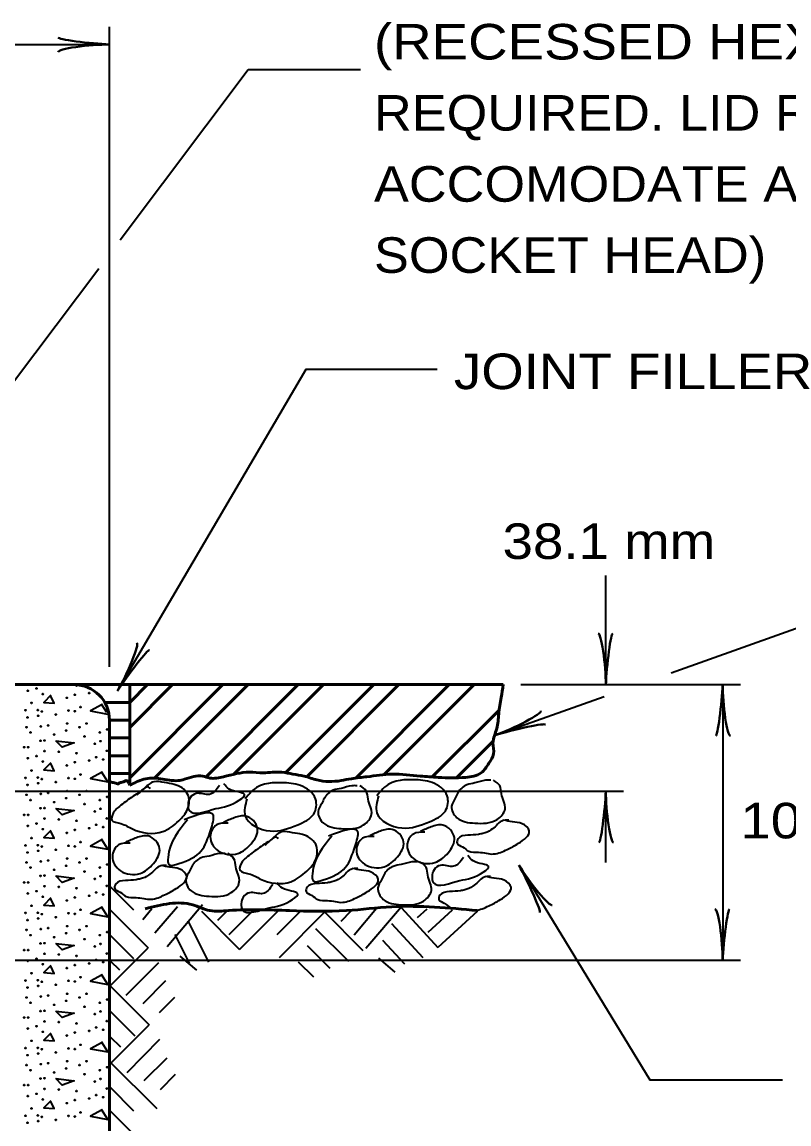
# Model space of a CAD drawing. Extents: x 442 to 1297, y -1132 to -588.
# Drawn here: x 669.8 to 721.6, y -913.9 to -839.5 of the extents above; entities that cross this region are included whole.
import ezdxf
from ezdxf.enums import TextEntityAlignment as Align

# ---------------------------------------------------------------- set-up
doc = ezdxf.new("R2010")
doc.units = 0
doc.header["$LTSCALE"] = 0.96
doc.layers.add('1', color=7, linetype='Continuous', lineweight=35)

msp = doc.modelspace()

# ---------------------------------------------------------------- linework, layer by layer
at = {"layer": '1'}
for p, q in [((675.7476, -883.0076), (675.7476, -839.8076)), ((570.1476, -841.0076), (675.7476, -841.0076)), ((676.4683, -854.1939), (685.1022, -842.7004)), ((685.1022, -842.7004), (692.699, -842.7004)), ((669.2683, -863.7786), (675.0268, -856.1125)), ((709.2608, -884.2076), (709.2608, -876.8344)), ((713.6649, -883.405), (726.825, -878.736)), ((703.5229, -884.2076), (718.3494, -884.2076)), ((717.1494, -884.2076), (717.1494, -902.8076)), ((701.7875, -887.6192), (709.1411, -885.01)), ((675.5776, -886.0926), (675.2138, -885.5267)), ((657.1476, -891.4076), (710.4608, -891.4076)), ((709.2608, -896.2076), (709.2608, -891.4076)), ((675.7956, -897.8235), (677.3796, -899.4075)), ((682.0321, -899.0677), (679.635, -901.908)), ((675.7956, -899.4075), (678.3636, -901.9755)), ((678.611, -899.3415), (677.9967, -900.0889)), ((680.3335, -899.2037), (678.8149, -900.9865)), ((681.9679, -899.5049), (684.5359, -902.0729)), ((683.6719, -899.5049), (683.0479, -900.1289)), ((685.3999, -899.5049), (683.8159, -901.0889)), ((687.1039, -899.5049), (684.5359, -902.0729)), ((688.6399, -899.5049), (687.0559, -901.0889)), ((690.3439, -899.5049), (687.1999, -902.6489)), ((690.2239, -899.5049), (692.8639, -902.1449)), ((692.0479, -899.5049), (691.3759, -900.2009)), ((693.7714, -899.3132), (692.2786, -901.1177)), ((695.4708, -899.2013), (693.0519, -902.023)), ((695.4663, -899.2778), (697.9177, -901.9573)), ((697.1686, -899.3535), (696.5175, -899.9491)), ((698.8949, -899.4302), (697.2421, -900.9423)), ((700.5972, -899.5059), (697.9177, -901.9573)), ((681.0476, -900.1544), (682.4436, -902.9475)), ((694.795, -900.329), (696.9027, -902.6329)), ((675.7956, -901.1115), (677.3796, -902.6955)), ((680.1595, -901.0726), (681.1306, -903.0156)), ((689.6479, -900.6569), (691.8799, -902.8649)), ((675.7956, -904.5435), (678.3636, -901.9755)), ((689.0959, -901.8089), (690.6319, -903.3449)), ((694.1923, -901.4553), (695.6586, -903.058)), ((661.3476, -902.8076), (718.3494, -902.8076)), ((675.7956, -902.8395), (676.4196, -903.4635)), ((680.5039, -902.5367), (681.615, -903.4831)), ((693.9159, -902.6584), (695.0196, -903.6133)), ((676.8756, -905.1675), (679.0836, -902.9595)), ((688.4959, -902.9129), (689.5279, -903.9209)), ((678.0276, -905.7195), (679.5636, -904.1835)), ((675.7956, -904.5435), (678.4356, -907.1595)), ((679.1316, -906.3435), (680.1636, -905.3115)), ((675.7956, -906.2475), (677.4516, -907.9035)), ((675.7956, -909.7995), (678.4356, -907.1595)), ((675.7956, -907.9755), (676.4916, -908.6475)), ((676.9476, -910.3755), (679.1556, -908.1435)), ((678.0996, -910.9275), (679.6356, -909.3915)), ((675.7956, -909.6795), (678.9396, -912.8235)), ((679.2036, -911.5275), (680.2116, -910.4955)), ((675.7956, -911.3835), (677.3796, -912.9675)), ((675.7956, -912.9675), (678.3636, -915.5355))]:
    msp.add_line(p, q, dxfattribs=at)
at = {"layer": '1', "lineweight": 53}
for p, q in [((673.3476, -884.2076), (668.5476, -884.2076)), ((673.3476, -884.2076), (702.3229, -884.2076)), ((677.1161, -884.2076), (677.1161, -891.0035)), ((677.1161, -885.4076), (678.3161, -884.2076)), ((677.1161, -887.1046), (680.0131, -884.2076)), ((677.1161, -890.4986), (683.4071, -884.2076)), ((678.7881, -890.5236), (685.1041, -884.2076)), ((682.2734, -890.4323), (688.4981, -884.2076)), ((684.104, -890.2987), (690.1951, -884.2076)), ((687.6375, -890.1592), (693.5891, -884.2076)), ((689.0695, -890.4242), (695.2861, -884.2076)), ((692.3704, -890.5173), (698.6801, -884.2076)), ((694.326, -890.2587), (700.3771, -884.2076)), ((675.4261, -885.4076), (677.1161, -885.4076)), ((697.5416, -890.4371), (702.0733, -885.9054)), ((675.7476, -980.7675), (675.7476, -886.6076)), ((675.7476, -886.6076), (675.7476, -980.8522)), ((675.7476, -886.6076), (677.1161, -886.6076)), ((675.7476, -887.8076), (677.1161, -887.8076)), ((699.1905, -890.4852), (701.6671, -888.0086)), ((675.7476, -889.0076), (677.1161, -889.0076)), ((675.7476, -890.2076), (677.1161, -890.2076))]:
    msp.add_line(p, q, dxfattribs=at)
at = {"layer": '1'}
for points in [[(676.293, -884.6252), (689.0246, -862.909), (697.8794, -862.909)], [(671.7818, -884.9267), (671.3258, -885.4067), (672.0218, -885.4547), (671.7818, -884.9747)], [(675.2618, -885.5507), (674.4698, -885.9827), (675.6105, -886.1922)], [(671.7818, -889.4867), (671.3258, -889.9667), (672.0218, -890.0147), (671.7818, -889.5347)], [(675.2618, -890.1107), (674.4698, -890.5427), (675.6458, -890.7587), (675.2138, -890.0867)], [(671.7818, -894.0467), (671.3258, -894.5267), (672.0218, -894.5747), (671.7818, -894.0947)], [(675.2618, -894.6707), (674.4698, -895.1027), (675.6458, -895.3187), (675.2138, -894.6467)], [(703.3988, -896.4034), (712.2296, -910.8809), (721.1831, -910.8809)], [(671.7818, -898.6067), (671.3258, -899.0867), (672.0218, -899.1347), (671.7818, -898.6547)], [(675.2618, -899.2307), (674.4698, -899.6627), (675.6458, -899.8787), (675.2138, -899.2067)], [(671.7818, -903.1667), (671.3258, -903.6467), (672.0218, -903.6947), (671.7818, -903.2147)], [(675.2618, -903.7907), (674.4698, -904.2227), (675.6458, -904.4387), (675.2138, -903.7667)], [(671.7818, -907.7267), (671.3258, -908.2067), (672.0218, -908.2547), (671.7818, -907.7747)], [(675.2618, -908.3507), (674.4698, -908.7827), (675.6458, -908.9987), (675.2138, -908.3267)], [(671.7818, -912.2867), (671.3258, -912.7667), (672.0218, -912.8147), (671.7818, -912.3347)], [(675.2618, -912.9107), (674.4698, -913.3427), (675.6458, -913.5587), (675.2138, -912.8867)]]:
    msp.add_lwpolyline(points, dxfattribs=at)
for points in [[(672.1178, -887.9987), (673.3658, -888.1427), (672.5498, -888.4307)], [(672.1178, -892.5587), (673.3658, -892.7027), (672.5498, -892.9907)], [(672.1178, -897.1187), (673.3658, -897.2627), (672.5498, -897.5507)], [(672.1178, -901.6787), (673.3658, -901.8227), (672.5498, -902.1107)], [(672.1178, -906.2387), (673.3658, -906.3827), (672.5498, -906.6707)], [(672.1178, -910.7987), (673.3658, -910.9427), (672.5498, -911.2307)]]:
    msp.add_lwpolyline(points, close=True, dxfattribs=at)
for centre in [(673.5268, -884.2752), (670.2255, -884.6195), (670.8139, -884.4661), (671.2525, -884.8421), (673.3996, -884.8899), (674.3697, -884.7785), (670.48, -885.4466), (672.8588, -885.0967), (673.7812, -885.7171), (670.0823, -885.9398), (670.2097, -886.4171), (670.9094, -885.9239), (670.9252, -886.3057), (671.1889, -886.0194), (672.1272, -886.2262), (672.986, -885.9558), (673.3996, -886.0035), (670.1459, -887.0852), (671.1161, -887.0216), (671.6182, -886.958), (672.8905, -886.8307), (673.7176, -887.0852), (674.1947, -886.8307), (675.5942, -887.2285), (670.4164, -887.4353), (671.0925, -887.9948), (671.3638, -887.9761), (672.0159, -887.5785), (672.827, -887.308), (674.0515, -887.7058), (675.1012, -887.4353), (675.149, -888.0239), (669.987, -888.4376), (670.2573, -888.4376), (671.3638, -888.6921), (672.334, -888.7398), (674.7672, -888.1989), (675.5624, -888.6762), (670.2255, -889.1795), (670.8139, -889.0261), (671.2525, -889.4021), (673.3996, -889.4499), (673.5268, -888.8352), (674.3697, -889.3385), (674.8468, -889.1057), (675.3238, -889.259), (670.48, -890.0066), (672.8588, -889.6567), (670.0823, -890.4998), (670.2097, -890.9771), (670.9094, -890.4839), (670.9252, -890.8657), (671.1889, -890.5794), (672.1272, -890.7862), (672.986, -890.5158), (673.3996, -890.5635), (673.7812, -890.2771), (670.1459, -891.6452), (671.1161, -891.5816), (671.6182, -891.518), (672.8905, -891.3907), (673.7176, -891.6452), (674.1947, -891.3907), (670.4164, -891.9953), (672.0159, -892.1385), (672.827, -891.868), (674.0515, -892.2658), (675.1012, -891.9953), (675.5942, -891.7885), (669.987, -892.9976), (670.2573, -892.9976), (671.0925, -892.5548), (671.3638, -892.5361), (674.7672, -892.7589), (675.149, -892.5839), (670.2255, -893.7395), (670.8139, -893.5861), (671.2525, -893.9621), (671.3638, -893.2521), (672.334, -893.2998), (673.5268, -893.3952), (674.3697, -893.8985), (674.8468, -893.6657), (675.3238, -893.819), (675.5624, -893.2362), (670.48, -894.5666), (672.8588, -894.2167), (673.3996, -894.0099), (670.0823, -895.0598), (670.9094, -895.0439), (670.9252, -895.4257), (671.1889, -895.1394), (672.1272, -895.3462), (672.986, -895.0758), (673.3996, -895.1235), (673.7812, -894.8371), (670.1459, -896.2052), (670.2097, -895.5371), (671.1161, -896.1416), (671.6182, -896.078), (672.8905, -895.9507), (673.7176, -896.2052), (674.1947, -895.9507), (670.4164, -896.5553), (672.0159, -896.6985), (672.827, -896.428), (674.0515, -896.8258), (675.1012, -896.5553), (675.5942, -896.3485), (669.987, -897.5576), (670.2573, -897.5576), (671.0925, -897.1148), (671.3638, -897.0961), (674.7672, -897.3189), (675.149, -897.1439), (670.2255, -898.2995), (670.8139, -898.1461), (671.3638, -897.8121), (672.334, -897.8598), (673.5268, -897.9552), (674.8468, -898.2257), (675.3238, -898.379), (675.5624, -897.7962), (670.48, -899.1266), (671.2525, -898.5221), (672.8588, -898.7767), (673.3996, -898.5699), (674.3697, -898.4585), (670.0823, -899.6198), (670.9094, -899.6039), (671.1889, -899.6994), (672.1272, -899.9062), (672.986, -899.6358), (673.3996, -899.6835), (673.7812, -899.3971), (670.2097, -900.0971), (670.9252, -899.9857), (671.6182, -900.638), (672.8905, -900.5107), (674.1947, -900.5107), (670.1459, -900.7652), (670.4164, -901.1153), (671.1161, -900.7016), (672.0159, -901.2585), (672.827, -900.988), (673.7176, -900.7652), (674.0515, -901.3858), (675.1012, -901.1153), (675.5942, -900.9085), (669.987, -902.1176), (670.2573, -902.1176), (671.0925, -901.6748), (671.3638, -901.6561), (674.7672, -901.8789), (675.149, -901.7039), (670.2255, -902.8595), (670.8139, -902.7061), (671.3638, -902.3721), (672.334, -902.4198), (673.5268, -902.5152), (674.8468, -902.7857), (675.5624, -902.3562), (671.2525, -903.0821), (672.8588, -903.3367), (673.3996, -903.1299), (674.3697, -903.0185), (675.3238, -902.939), (670.0823, -904.1798), (670.48, -903.6866), (670.9094, -904.1639), (671.1889, -904.2594), (672.986, -904.1958), (673.3996, -904.2435), (673.7812, -903.9571), (670.2097, -904.6571), (670.9252, -904.5457), (672.1272, -904.4662), (672.8905, -905.0707), (674.1947, -905.0707), (670.1459, -905.3252), (670.4164, -905.6753), (671.1161, -905.2616), (671.6182, -905.198), (672.0159, -905.8185), (672.827, -905.548), (673.7176, -905.3252), (675.1012, -905.6753), (675.5942, -905.4685), (671.0925, -906.2348), (671.3638, -906.2161), (674.0515, -905.9458), (674.7672, -906.4389), (675.149, -906.2639), (669.987, -906.6776), (670.2573, -906.6776), (670.8139, -907.2661), (671.3638, -906.9321), (672.334, -906.9798), (673.5268, -907.0752), (674.8468, -907.3457), (675.5624, -906.9162), (670.2255, -907.4195), (671.2525, -907.6421), (672.8588, -907.8967), (673.3996, -907.6899), (674.3697, -907.5785), (675.3238, -907.499), (670.0823, -908.7398), (670.48, -908.2466), (670.9094, -908.7239), (671.1889, -908.8194), (672.986, -908.7558), (673.3996, -908.8035), (673.7812, -908.5171), (670.2097, -909.2171), (670.9252, -909.1057), (672.1272, -909.0262), (670.1459, -909.8852), (670.4164, -910.2353), (671.1161, -909.8216), (671.6182, -909.758), (672.827, -910.108), (672.8905, -909.6307), (673.7176, -909.8852), (674.1947, -909.6307), (675.1012, -910.2353), (675.5942, -910.0285), (671.0925, -910.7948), (671.3638, -910.7761), (672.0159, -910.3785), (674.0515, -910.5058), (674.7672, -910.9989), (675.149, -910.8239), (669.987, -911.2376), (670.2573, -911.2376), (670.8139, -911.8261), (671.3638, -911.4921), (672.334, -911.5398), (673.5268, -911.6352), (675.5624, -911.4762), (670.2255, -911.9795), (671.2525, -912.2021), (672.8588, -912.4567), (673.3996, -912.2499), (674.3697, -912.1385), (674.8468, -911.9057), (675.3238, -912.059), (670.0823, -913.2998), (670.48, -912.8066), (670.9094, -913.2839), (672.986, -913.3158), (673.7812, -913.0771), (670.2097, -913.7771), (670.9252, -913.6657), (671.1889, -913.3794), (672.1272, -913.5862), (673.3996, -913.3635)]:
    msp.add_circle(centre, 0.0318, dxfattribs=at)
msp.add_arc((672.334, -884.1798), 0.0318, 241.23077, 298.76923, dxfattribs=at)
at = {"layer": '1', "lineweight": 53}
msp.add_arc((673.3476, -886.6076), 2.4, 0, 90, dxfattribs=at)
at = {"layer": '1', "lineweight": 40}
for centre, major_axis, ratio, start_param, end_param in [((674.4274, -841.3295), (2.1428, 0.1874), 0.122415, 0.8963533, 3.1415927), ((674.3922, -840.744), (2.1077, -0.2108), 0.07063, 3.1407148, 5.41811), ((708.9292, -882.8982), (0.1874, -2.1428), 0.122415, 0.8963533, 3.1415927), ((709.5147, -882.863), (-0.2108, -2.1077), 0.07063, 3.1407148, 5.41811), ((676.6692, -883.3279), (-0.9221, -1.9433), 0.122415, 0.8963533, 3.1415927), ((677.1921, -883.5937), (-1.2478, -1.7117), 0.07063, 3.1407148, 5.41811), ((716.8955, -885.5522), (0.2108, 2.1077), 0.07063, 3.1407148, 5.41811), ((716.8955, -885.5522), (0.2108, 2.1077), 0.07063, 3.1407148, 5.41811), ((717.481, -885.517), (-0.1874, 2.1428), 0.122415, 0.8963533, 3.1415927), ((717.481, -885.517), (-0.1874, 2.1428), 0.122415, 0.8963533, 3.1415927), ((702.9107, -886.8689), (-1.9568, -0.8931), 0.122415, 0.8963533, 3.1415927), ((703.1396, -887.4089), (-2.0569, -0.5061), 0.07063, 3.1407148, 5.41811), ((709.0069, -892.7522), (0.2108, 2.1077), 0.07063, 3.1407148, 5.41811), ((709.0069, -892.7522), (0.2108, 2.1077), 0.07063, 3.1407148, 5.41811), ((709.5924, -892.717), (-0.1874, 2.1428), 0.122415, 0.8963533, 3.1415927), ((709.5924, -892.717), (-0.1874, 2.1428), 0.122415, 0.8963533, 3.1415927), ((703.8822, -897.6835), (-0.9176, 1.9092), 0.07063, 3.1407148, 5.41811), ((704.3637, -897.3486), (-1.2758, 1.7318), 0.122415, 0.8963533, 3.1415927), ((716.8178, -901.4982), (0.1874, -2.1428), 0.122415, 0.8963533, 3.1415927), ((716.8178, -901.4982), (0.1874, -2.1428), 0.122415, 0.8963533, 3.1415927), ((717.4033, -901.463), (-0.2108, -2.1077), 0.07063, 3.1407148, 5.41811), ((717.4033, -901.463), (-0.2108, -2.1077), 0.07063, 3.1407148, 5.41811)]:
    msp.add_ellipse(centre, major_axis=major_axis, ratio=ratio, start_param=start_param, end_param=end_param, dxfattribs=at)
at = {"layer": '1', "lineweight": 53}
for points in [[(677.1161, -891.0035), (678.057, -890.5981), (679.1965, -890.5543), (680.3798, -890.6858), (680.818, -890.5981), (682.0451, -890.3789), (682.5272, -890.5105), (683.4476, -890.4228), (685.2006, -890.1159), (686.1209, -890.1597), (687.3919, -890.1159), (688.1369, -890.2474), (688.8819, -890.3789), (689.7584, -890.642), (691.38, -890.6858), (692.0812, -890.5543), (693.133, -890.4228), (694.8422, -890.2474), (696.7267, -890.3789), (697.9538, -890.4666), (699.7945, -890.4666), (700.8463, -890.1597), (701.3722, -889.5022), (701.679, -888.8884), (701.6352, -888.1431), (701.8981, -887.1786), (702.0296, -886.1703), (702.2049, -885.0743), (702.3229, -884.2076)], [(677.1161, -891.0035), (676.8737, -890.6858), (676.6984, -890.7735), (676.3916, -890.8612), (676.3478, -890.905), (676.304, -890.905), (676.1725, -890.8612), (675.9972, -890.8173), (675.7781, -890.7735)], [(700.5754, -899.4569), (694.8136, -899.2007), (691.7406, -899.4569), (687.8993, -899.4569), (683.802, -899.4569), (682.5216, -899.4569), (681.3693, -899.0726), (678.1682, -899.3288)]]:
    msp.add_spline(points, degree=3, dxfattribs=at)
at = {"layer": '1'}
for points in [[(678.5001, -891.2385), (678.3798, -891.1182), (678.079, -891.2385), (677.1167, -891.9001), (676.3347, -892.5016), (676.0941, -892.7422), (675.9137, -893.3437), (676.5152, -893.5843), (677.2971, -893.9452), (679.3422, -894.1256), (680.4248, -893.4038), (681.0263, -892.6219), (681.0263, -891.5994), (680.1241, -890.9377), (679.4625, -890.8175), (678.7407, -890.7573), (678.1392, -891.1783), (677.5978, -891.6595)], [(683.173, -891.0125), (682.5113, -891.614), (681.6091, -891.5539), (681.1881, -891.8546), (681.1279, -892.6967), (682.9324, -892.5764), (683.7143, -892.396), (684.8571, -891.614), (683.8346, -891.2531), (683.4737, -890.8922)], [(685.0268, -891.9178), (684.9065, -893.0606), (686.5907, -894.0832), (688.4553, -893.6621), (689.538, -892.9403), (689.6583, -891.9178), (688.6358, -891.0156), (687.3726, -890.8351), (686.3501, -890.8953), (685.8088, -891.0757), (684.9065, -891.9178)], [(693.9165, -891.7138), (693.7962, -892.8566), (695.4804, -893.8792), (697.345, -893.4581), (698.4277, -892.7363), (698.548, -891.7138), (697.5255, -890.8116), (696.2623, -890.6311), (695.2398, -890.6913), (694.6985, -890.8717), (693.7962, -891.7138)], [(701.4943, -890.6652), (701.1334, -890.6652), (700.4116, -890.8456), (699.8702, -890.9659), (699.2688, -891.5073), (699.0883, -891.8682), (698.8477, -892.4095), (699.2086, -893.1914), (700.4116, -893.5523), (701.9153, -893.3117), (702.4566, -892.59), (702.216, -891.5674), (702.0958, -891.0261), (701.6747, -890.6652)], [(692.4822, -891.0323), (692.1213, -891.0323), (691.3995, -891.2127), (690.8581, -891.333), (690.2567, -891.8744), (690.0762, -892.2353), (689.8356, -892.7766), (690.1965, -893.5585), (691.3995, -893.9194), (692.9032, -893.6788), (693.4445, -892.9571), (693.2039, -891.9345), (693.0837, -891.3932), (692.6626, -891.0323)], [(681.023, -893.3421), (679.6998, -895.8684), (679.7599, -896.3496), (680.4215, -896.2894), (681.9253, -895.4474), (682.5869, -894.0038), (682.7673, -893.0414), (680.7824, -893.3421)], [(683.7556, -893.5574), (682.9736, -893.6777), (682.5526, -894.4597), (683.0939, -895.422), (684.4172, -895.6025), (685.3194, -894.9408), (685.7405, -893.9183), (684.9585, -893.0762), (684.1766, -893.1965), (683.4548, -893.4973)], [(690.7691, -894.4435), (689.4459, -896.9698), (689.506, -897.451), (690.1676, -897.3908), (691.6714, -896.5488), (692.333, -895.1052), (692.5134, -894.1428), (690.5285, -894.4435)], [(693.6241, -894.4549), (692.8421, -894.5752), (692.4211, -895.3572), (692.9624, -896.3195), (694.2857, -896.5), (695.1879, -895.8383), (695.609, -894.8158), (694.827, -893.9737), (694.0451, -894.094), (693.3233, -894.3948)], [(697.0494, -894.1693), (696.2674, -894.2896), (695.8464, -895.0716), (696.3877, -896.0339), (697.711, -896.2144), (698.6132, -895.5527), (699.0343, -894.5302), (698.2523, -893.6881), (697.4704, -893.8084), (696.7486, -894.1092)], [(702.7099, -893.3511), (702.2287, -893.4113), (701.8679, -893.712), (701.507, -894.0128), (700.9656, -894.2533), (700.6649, -894.3135), (699.9431, -894.3736), (699.2815, -894.6142), (699.2213, -894.915), (699.5822, -895.1556), (700.0032, -895.4563), (700.6649, -895.5165), (701.6874, -895.6368), (702.5896, -895.336), (703.3716, -894.915), (704.0934, -894.0729), (703.6122, -893.5917), (702.9505, -893.4714), (702.349, -893.3511)], [(677.1495, -894.9036), (676.3675, -895.0239), (675.9465, -895.8059), (676.4878, -896.7682), (677.8111, -896.9487), (678.7133, -896.287), (679.1344, -895.2645), (678.3524, -894.4224), (677.5705, -894.5427), (676.8487, -894.8435)], [(687.1452, -894.6242), (687.0249, -894.5039), (686.7241, -894.6242), (685.7618, -895.2858), (684.9798, -895.8873), (684.7392, -896.1279), (684.5588, -896.7294), (685.1603, -896.97), (685.9422, -897.3309), (687.9873, -897.5113), (689.0699, -896.7895), (689.6714, -896.0076), (689.6714, -894.9851), (688.7692, -894.3234), (688.1076, -894.2032), (687.3858, -894.143), (686.7843, -894.564), (686.2429, -895.0452)], [(683.5517, -895.601), (683.1908, -895.601), (682.469, -895.7814), (681.9276, -895.9017), (681.3262, -896.4431), (681.1457, -896.804), (680.9051, -897.3453), (681.266, -898.1272), (682.469, -898.4881), (683.9727, -898.2475), (684.514, -897.5258), (684.2734, -896.5032), (684.1532, -895.9619), (683.7321, -895.601)], [(696.5193, -896.1721), (696.1584, -896.1721), (695.4366, -896.3525), (694.8952, -896.4728), (694.2938, -897.0142), (694.1133, -897.3751), (693.8727, -897.9164), (694.2336, -898.6983), (695.4366, -899.0592), (696.9403, -898.8186), (697.4816, -898.0969), (697.241, -897.0743), (697.1208, -896.533), (696.6997, -896.1721)], [(699.6476, -895.8667), (698.9859, -896.4682), (698.0837, -896.4081), (697.6627, -896.7088), (697.6025, -897.5509), (699.407, -897.4306), (700.1889, -897.2502), (701.3317, -896.4682), (700.3092, -896.1073), (699.9483, -895.7464)], [(679.5885, -896.4105), (679.1073, -896.4707), (678.7465, -896.7714), (678.3856, -897.0722), (677.8442, -897.3127), (677.5435, -897.3729), (676.8217, -897.433), (676.1601, -897.6736), (676.0999, -897.9744), (676.4608, -898.215), (676.8818, -898.5157), (677.5435, -898.5759), (678.566, -898.6962), (679.4682, -898.3954), (680.2502, -897.9744), (680.972, -897.1323), (680.4908, -896.6511), (679.8291, -896.5308), (679.2276, -896.4105)], [(692.5153, -896.6145), (692.0341, -896.6747), (691.6733, -896.9754), (691.3124, -897.2762), (690.771, -897.5167), (690.4703, -897.5769), (689.7485, -897.637), (689.0869, -897.8776), (689.0267, -898.1784), (689.3876, -898.419), (689.8086, -898.7197), (690.4703, -898.7799), (691.4928, -898.9002), (692.395, -898.5994), (693.177, -898.1784), (693.8988, -897.3363), (693.4176, -896.8551), (692.7559, -896.7348), (692.1544, -896.6145)], [(686.7692, -897.7071), (686.1075, -898.3086), (685.2053, -898.2485), (684.7843, -898.5492), (684.7241, -899.3913), (686.5286, -899.271), (687.3105, -899.0906), (688.4533, -898.3086), (687.4308, -897.9477), (687.0699, -897.5868)], [(701.4834, -897.1545), (701.0022, -897.2147), (700.6414, -897.5154), (700.2805, -897.8162), (699.7391, -898.0567), (699.4384, -898.1169), (698.7166, -898.177), (698.055, -898.4176), (697.9948, -898.7184), (698.3557, -898.959), (698.7767, -899.2597), (699.4384, -899.3199), (700.4609, -899.4402), (701.3631, -899.1394), (702.1451, -898.7184), (702.8669, -897.8763), (702.3857, -897.3951), (701.724, -897.2748), (701.1225, -897.1545)]]:
    msp.add_spline(points, degree=3, dxfattribs=at)

# ---------------------------------------------------------------- texts
for s, width, p in [('(RECESSED HEX-HEAD BOLT', 1.15, (693.6064, -842.0146)), ('REQUIRED. LID RECESS MUST', 1.1, (693.6064, -846.8146)), ('ACCOMODATE A STANDARD', 1.1, (693.6064, -851.6146)), ('SOCKET HEAD)', 1.1, (693.6064, -856.4146)), ('JOINT FILLER', 1.15, (699.0033, -864.2624))]:
    msp.add_text(s, height=2.4, dxfattribs=dict(at, width=width)).set_placement(p)
at = {"layer": '1', "width": 1.15}
for s, p in [('38.1 mm', (709.4672, -875.7253)), ('101.6 mm', (726.5513, -894.5836))]:
    msp.add_text(s, height=2.4, dxfattribs=at).set_placement(p, align=Align.CENTER)

doc.saveas('drawing.dxf')
